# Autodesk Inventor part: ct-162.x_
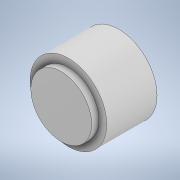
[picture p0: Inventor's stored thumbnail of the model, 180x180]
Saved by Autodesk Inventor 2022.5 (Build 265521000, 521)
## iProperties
Created: 2023-06
Part Number: ct-162.x_
Material: Generic
Document SubType Name: Modeling
Designer: ImaoCorp
Density: 1 g/cm^3
Appearance: Default
Sending System: SOLIDWORKS 2021-2021301
MC: AMD64
MC_MODEL: Intel64 Family 6 Model 60 Stepping 3, GenuineIntel
OS: Windows_NT
FRU: Parasolid Version 32.1, build 255,  1- 1-2021
FORMAT: text
GUISE: transmit
KEY: ct-162
FILE: ct-162.x_t
DATE: Thu Jun 15 15:47:22 2023
Author: ImaoCorp
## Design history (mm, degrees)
feature "Base1"
node "ソリッド1"
